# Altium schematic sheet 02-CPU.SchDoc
size A2
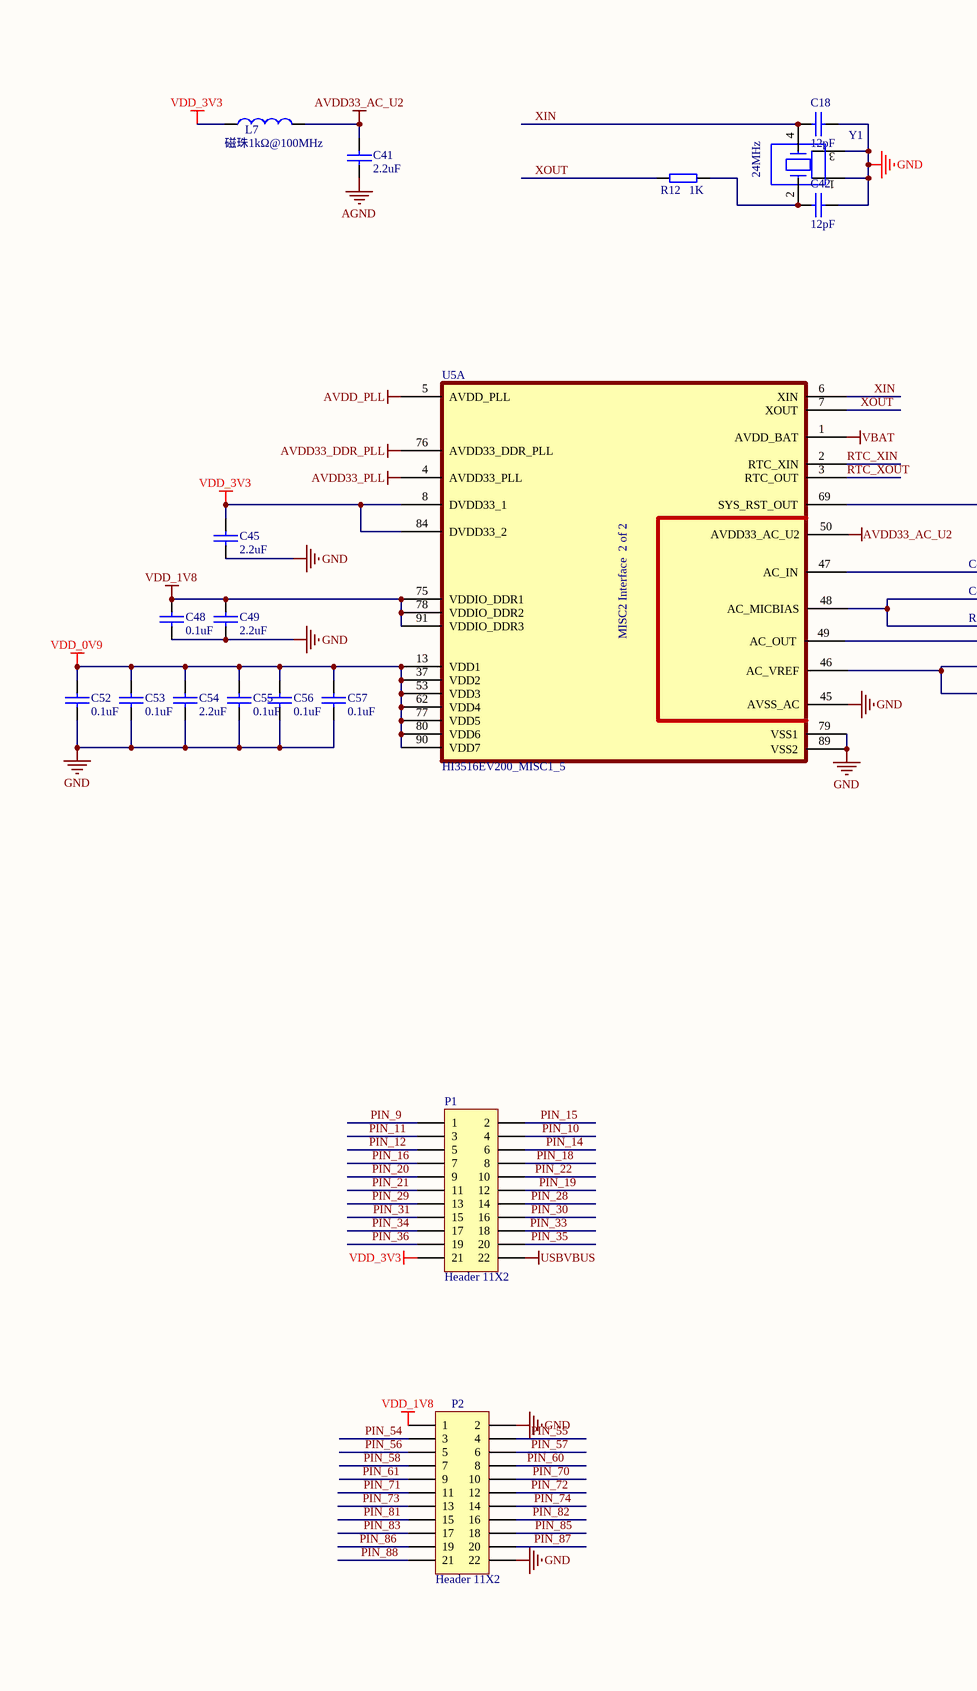
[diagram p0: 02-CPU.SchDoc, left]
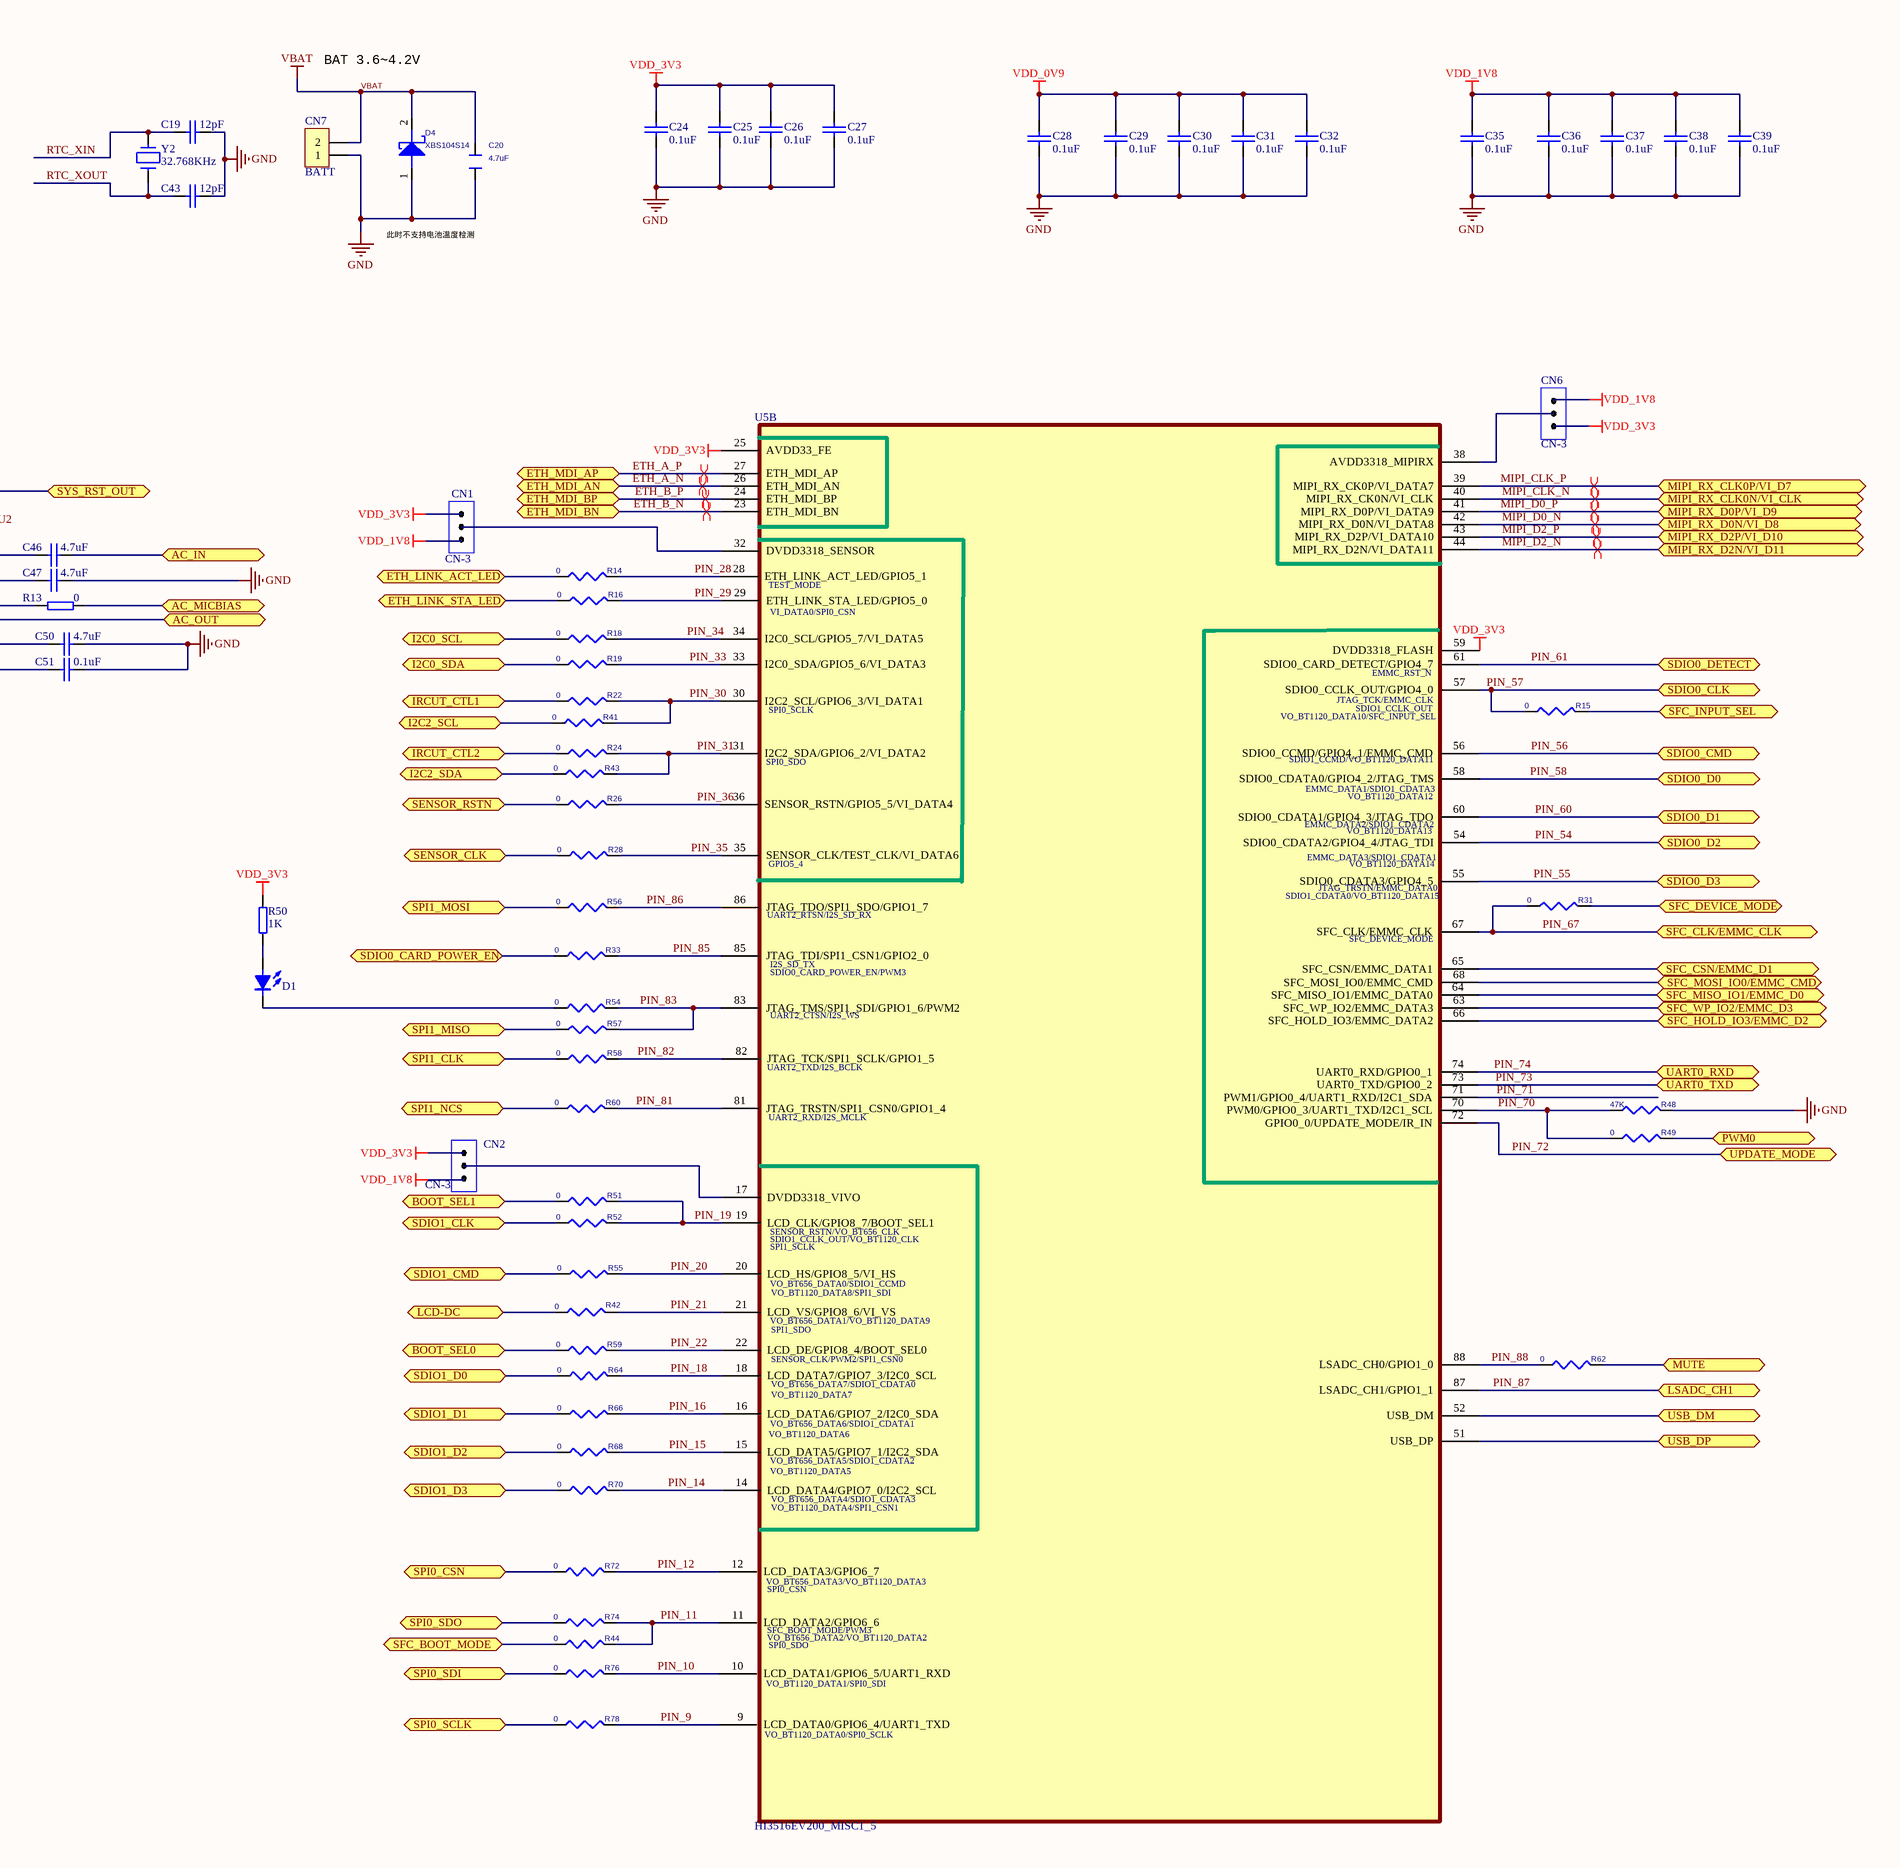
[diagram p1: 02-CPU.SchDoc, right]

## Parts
C18  12pF  [C0402]
C19  12pF  [C0402]
C20  4.7uF  [C0402]
C24  0.1uF  [C0402]
C25  0.1uF  [C0402]
C26  0.1uF  [C0402]
C27  0.1uF  [C0402]
C28  0.1uF  [C0402]
C29  0.1uF  [C0402]
C30  0.1uF  [C0402]
C31  0.1uF  [C0402]
C32  0.1uF  [C0402]
C35  0.1uF  [C0402]
C36  0.1uF  [C0402]
C37  0.1uF  [C0402]
C38  0.1uF  [C0402]
C39  0.1uF  [C0402]
C41  2.2uF  [C0402]
C42  12pF  [C0402]
C43  12pF  [C0402]
C45  2.2uF  [C0402]
C46  4.7uF  [C0402]
C47  4.7uF  [C0402]
C48  0.1uF  [C0402]
C49  2.2uF  [C0402]
C50  4.7uF  [C0402]
C51  0.1uF  [C0402]
C52  0.1uF  [C0402]
C53  0.1uF  [C0402]
C54  2.2uF  [C0402]
C55  0.1uF  [C0402]
C56  0.1uF  [C0402]
C57  0.1uF  [C0402]
CN1  CN-3  [SIP3(1.27_SMD)]
CN2  CN-3  [SIP3(1.27_SMD)]
CN6  CN-3  [SIP3(1.27_SMD)]
CN7  BATT  [PH-2A]
D1  二极管(LED,红色)  [D0603]  (value not drawn)
D4  XBS104S14  [SOD-123]
L7  磁珠1kΩ@100MHz  [L0603]
P1  Header 11X2  [HDR2X11]
P2  Header 11X2  [HDR2X11]
R12  1K  [R0402]
R13  0  [R0402]
R14  0  [R0402]
R15  0  [R0402]
R16  0  [R0402]
R18  0  [R0402]
R19  0  [R0402]
R22  0  [R0402]
R24  0  [R0402]
R26  0  [R0402]
R28  0  [R0402]
R31  0  [R0402]
R33  0  [R0402]
R41  0  [R0402]
R42  0  [R0402]
R43  0  [R0402]
R44  0  [R0402]
R48  47K  [R0402]
R49  0  [R0402]
R50  1K  [R0402]
R51  0  [R0402]
R52  0  [R0402]
R54  0  [R0402]
R55  0  [R0402]
R56  0  [R0402]
R57  0  [R0402]
R58  0  [R0402]
R59  0  [R0402]
R60  0  [R0402]
R62  0  [R0402]
R64  0  [R0402]
R66  0  [R0402]
R68  0  [R0402]
R70  0  [R0402]
R72  0  [R0402]
R74  0  [R0402]
R76  0  [R0402]
R78  0  [R0402]
U5  HI3516EV200_MISC1_5  [V200_MLF88-035-0909L]  (parts A,B of 2)
Y1  24MHz  [XTAL(3*2.5)]
Y2  32.768KHz  [FC-135]

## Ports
AC_IN (bidir), AC_MICBIAS (bidir), AC_OUT (bidir), BOOT_SEL0 (bidir), BOOT_SEL1 (bidir), ETH_LINK_ACT_LED (bidir), ETH_LINK_STA_LED (bidir), ETH_MDI_AN (bidir), ETH_MDI_AP (bidir), ETH_MDI_BN (bidir), ETH_MDI_BP (bidir), I2C0_SCL (bidir), I2C0_SDA (bidir), I2C2_SCL (bidir), I2C2_SDA (bidir), IRCUT_CTL1 (bidir), IRCUT_CTL2 (bidir), LCD-DC (bidir), LSADC_CH1 (bidir), MIPI_RX_CLK0N/VI_CLK (bidir), MIPI_RX_CLK0P/VI_D7 (bidir), MIPI_RX_D0N/VI_D8 (bidir), MIPI_RX_D0P/VI_D9 (bidir), MIPI_RX_D2N/VI_D11 (bidir), MIPI_RX_D2P/VI_D10 (bidir), MUTE (bidir), PWM0 (bidir), SDIO0_CARD_POWER_EN (bidir), SDIO0_CLK (bidir), SDIO0_CMD (bidir), SDIO0_D0 (bidir), SDIO0_D1 (bidir), SDIO0_D2 (bidir), SDIO0_D3 (bidir), SDIO0_DETECT (bidir), SDIO1_CLK (bidir), SDIO1_CMD (bidir), SDIO1_D0 (bidir), SDIO1_D1 (bidir), SDIO1_D2 (bidir), SDIO1_D3 (bidir), SENSOR_CLK (bidir), SENSOR_RSTN (bidir), SFC_BOOT_MODE (bidir), SFC_CLK/EMMC_CLK (bidir), SFC_CSN/EMMC_D1 (bidir), SFC_DEVICE_MODE (bidir), SFC_HOLD_IO3/EMMC_D2 (bidir), SFC_INPUT_SEL (bidir), SFC_MISO_IO1/EMMC_D0 (bidir), SFC_MOSI_IO0/EMMC_CMD (bidir), SFC_WP_IO2/EMMC_D3 (bidir), SPI0_CSN (bidir), SPI0_SCLK (bidir), SPI0_SDI (bidir), SPI0_SDO (bidir), SPI1_CLK (bidir), SPI1_MISO (bidir), SPI1_MOSI (bidir), SPI1_NCS (bidir), SYS_RST_OUT (bidir), UART0_RXD (bidir), UART0_TXD (bidir), UPDATE_MODE (bidir), USB_DM (bidir), USB_DP (bidir)

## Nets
AGND: C41.2
AVDD33_AC_U2: C41.1 L7.2 U5.50(AVDD33_AC_U2)
AVDD33_DDR_PLL: U5.76(AVDD33_DDR_PLL)
AVDD33_PLL: U5.4(AVDD33_PLL)
AVDD_PLL: U5.5(AVDD_PLL)
GND: C18.2 C19.2 C20.1 C24.1 C25.1 C26.1 C27.1 C28.1 C29.1 C30.1 C31.1 C32.1 C35.1 C36.1 C37.1 C38.1 C39.1 C42.2 C43.2 C45.1 C47.2 C48.2 C49.1 C50.2 C51.2 C52.2 C53.2 C54.1 C55.2 C56.2 C57.2 CN7.1 D4.1 P2.2 P2.22 R48.1 U5.45(AVSS_AC) U5.79(VSS1) U5.89(VSS2) Y1.1 Y1.3
USBVBUS: P1.22
VBAT: C20.2 CN7.2 D4.2 U5.1(AVDD_BAT)
VDD_0V9: C28.2 C29.2 C30.2 C31.2 C32.2 C52.1 C53.1 C54.2 C55.1 C56.1 C57.1 U5.13(VDD1) U5.37(VDD2) U5.53(VDD3) U5.62(VDD4) U5.77(VDD5) U5.80(VDD6) U5.90(VDD7)
VDD_1V8: C35.2 C36.2 C37.2 C38.2 C39.2 C48.1 C49.2 CN1.3 CN2.3 CN6.3 P2.1 U5.75(VDDIO_DDR1) U5.78(VDDIO_DDR2) U5.91(VDDIO_DDR3)
VDD_3V3: C24.2 C25.2 C26.2 C27.2 C45.2 CN1.1 CN2.1 CN6.1 L7.1 P1.21 R50.1 U5.8(DVDD33_1) U5.25(AVDD33_FE) U5.59(DVDD3318_FLASH) U5.84(DVDD33_2)
AC_IN: C46.2 ; port AC_IN
AC_MICBIAS: R13.1 ; port AC_MICBIAS
AC_OUT: U5.49(AC_OUT) ; port AC_OUT
BOOT_SEL0: R59.2 ; port BOOT_SEL0
BOOT_SEL1: R51.2 ; port BOOT_SEL1
ETH_A_N: U5.26(ETH_MDI_AN) ; port ETH_MDI_AN
ETH_A_P: U5.27(ETH_MDI_AP) ; port ETH_MDI_AP
ETH_B_N: U5.23(ETH_MDI_BN) ; port ETH_MDI_BN
ETH_B_P: U5.24(ETH_MDI_BP) ; port ETH_MDI_BP
ETH_LINK_ACT_LED: R14.2 ; port ETH_LINK_ACT_LED
ETH_LINK_STA_LED: R16.2 ; port ETH_LINK_STA_LED
I2C0_SCL: R18.2 ; port I2C0_SCL
I2C0_SDA: R19.2 ; port I2C0_SDA
I2C2_SCL: R41.2 ; port I2C2_SCL
I2C2_SDA: R43.2 ; port I2C2_SDA
IRCUT_CTL1: R22.2 ; port IRCUT_CTL1
IRCUT_CTL2: R24.2 ; port IRCUT_CTL2
LCD-DC: R42.2 ; port LCD-DC
MIPI_CLK_N: U5.40(MIPI_RX_CK0N/VI_CLK) ; port MIPI_RX_CLK0N/VI_CLK
MIPI_CLK_P: U5.39(MIPI_RX_CK0P/VI_DATA7) ; port MIPI_RX_CLK0P/VI_D7
MIPI_D0_N: U5.42(MIPI_RX_D0N/VI_DATA8) ; port MIPI_RX_D0N/VI_D8
MIPI_D0_P: U5.41(MIPI_RX_D0P/VI_DATA9) ; port MIPI_RX_D0P/VI_D9
MIPI_D2_N: U5.44(MIPI_RX_D2N/VI_DATA11) ; port MIPI_RX_D2N/VI_D11
MIPI_D2_P: U5.43(MIPI_RX_D2P/VI_DATA10) ; port MIPI_RX_D2P/VI_D10
MUTE: R62.1 ; port MUTE
PIN_9: P1.1 R78.1 U5.9(LCD_DATA0/GPIO6_4/UART1_TXD)
PIN_10: P1.4 R76.1 U5.10(LCD_DATA1/GPIO6_5/UART1_RXD)
PIN_11: P1.3 R44.1 R74.1 U5.11(LCD_DATA2/GPIO6_6)
PIN_12: P1.5 R72.1 U5.12(LCD_DATA3/GPIO6_7)
PIN_14: P1.6 R70.1 U5.14(LCD_DATA4/GPIO7_0/I2C2_SCL)
PIN_15: P1.2 R68.1 U5.15(LCD_DATA5/GPIO7_1/I2C2_SDA)
PIN_16: P1.7 R66.1 U5.16(LCD_DATA6/GPIO7_2/I2C0_SDA)
PIN_18: P1.8 R64.1 U5.18(LCD_DATA7/GPIO7_3/I2C0_SCL)
PIN_19: P1.12 R51.1 R52.1 U5.19(LCD_CLK/GPIO8_7/BOOT_SEL1)
PIN_20: P1.9 R55.1 U5.20(LCD_HS/GPIO8_5/VI_HS)
PIN_21: P1.11 R42.1 U5.21(LCD_VS/GPIO8_6/VI_VS)
PIN_22: P1.10 R59.1 U5.22(LCD_DE/GPIO8_4/BOOT_SEL0)
PIN_28: P1.14 R14.1 U5.28(ETH_LINK_ACT_LED/GPIO5_1)
PIN_29: P1.13 R16.1 U5.29(ETH_LINK_STA_LED/GPIO5_0)
PIN_30: P1.16 R22.1 R41.1 U5.30(I2C2_SCL/GPIO6_3/VI_DATA1)
PIN_31: P1.15 R24.1 R43.1 U5.31(I2C2_SDA/GPIO6_2/VI_DATA2)
PIN_33: P1.18 R19.1 U5.33(I2C0_SDA/GPIO5_6/VI_DATA3)
PIN_34: P1.17 R18.1 U5.34(I2C0_SCL/GPIO5_7/VI_DATA5)
PIN_35: P1.20 R28.1 U5.35(SENSOR_CLK/TEST_CLK/VI_DATA6)
PIN_36: P1.19 R26.1 U5.36(SENSOR_RSTN/GPIO5_5/VI_DATA4)
PIN_54: P2.3 U5.54(SDIO0_CDATA2/GPIO4_4/JTAG_TDI) ; port SDIO0_D2
PIN_55: P2.4 U5.55(SDIO0_CDATA3/GPIO4_5) ; port SDIO0_D3
PIN_56: P2.5 U5.56(SDIO0_CCMD/GPIO4_1/EMMC_CMD) ; port SDIO0_CMD
PIN_57: P2.6 R15.2 U5.57(SDIO0_CCLK_OUT/GPIO4_0) ; port SDIO0_CLK
PIN_58: P2.7 U5.58(SDIO0_CDATA0/GPIO4_2/JTAG_TMS) ; port SDIO0_D0
PIN_60: P2.8 U5.60(SDIO0_CDATA1/GPIO4_3/JTAG_TDO) ; port SDIO0_D1
PIN_61: P2.9 U5.61(SDIO0_CARD_DETECT/GPIO4_7) ; port SDIO0_DETECT
PIN_67: R31.2 U5.67(SFC_CLK/EMMC_CLK) ; port SFC_CLK/EMMC_CLK
PIN_70: P2.10 R48.2 R49.2 U5.70(PWM0/GPIO0_3/UART1_TXD/I2C1_SCL)
PIN_71: P2.11 U5.71(PWM1/GPIO0_4/UART1_RXD/I2C1_SDA)
PIN_72: P2.12 U5.72(GPIO0_0/UPDATE_MODE/IR_IN) ; port UPDATE_MODE
PIN_73: P2.13 U5.73(UART0_TXD/GPIO0_2) ; port UART0_TXD
PIN_74: P2.14 U5.74(UART0_RXD/GPIO0_1) ; port UART0_RXD
PIN_81: P2.15 R60.1 U5.81(JTAG_TRSTN/SPI1_CSN0/GPIO1_4)
PIN_82: P2.16 R58.1 U5.82(JTAG_TCK/SPI1_SCLK/GPIO1_5)
PIN_83: P2.17 R54.1 R57.1 U5.83(JTAG_TMS/SPI1_SDI/GPIO1_6/PWM2)
PIN_85: P2.18 R33.1 U5.85(JTAG_TDI/SPI1_CSN1/GPIO2_0)
PIN_86: P2.19 R56.1 U5.86(JTAG_TDO/SPI1_SDO/GPIO1_7)
PIN_87: P2.20 U5.87(LSADC_CH1/GPIO1_1) ; port LSADC_CH1
PIN_88: P2.21 R62.2 U5.88(LSADC_CH0/GPIO1_0)
PWM0: R49.1 ; port PWM0
RTC_XIN: C19.1 U5.2(RTC_XIN) Y2.2
RTC_XOUT: C43.1 U5.3(RTC_OUT) Y2.1
SDIO0_CARD_POWER_EN: R33.2 ; port SDIO0_CARD_POWER_EN
SDIO1_CLK: R52.2 ; port SDIO1_CLK
SDIO1_CMD: R55.2 ; port SDIO1_CMD
SDIO1_D0: R64.2 ; port SDIO1_D0
SDIO1_D1: R66.2 ; port SDIO1_D1
SDIO1_D2: R68.2 ; port SDIO1_D2
SDIO1_D3: R70.2 ; port SDIO1_D3
SENSOR_CLK: R28.2 ; port SENSOR_CLK
SENSOR_RSTN: R26.2 ; port SENSOR_RSTN
SFC_BOOT_MODE: R44.2 ; port SFC_BOOT_MODE
SFC_CSN/EMMC_D1: U5.65(SFC_CSN/EMMC_DATA1) ; port SFC_CSN/EMMC_D1
SFC_DEVICE_MODE: R31.1 ; port SFC_DEVICE_MODE
SFC_HOLD_IO3/EMMC_D2: U5.66(SFC_HOLD_IO3/EMMC_DATA2) ; port SFC_HOLD_IO3/EMMC_D2
SFC_INPUT_SEL: R15.1 ; port SFC_INPUT_SEL
SFC_MISO_IO1/EMMC_D0: U5.64(SFC_MISO_IO1/EMMC_DATA0) ; port SFC_MISO_IO1/EMMC_D0
SFC_MOSI_IO0/EMMC_CMD: U5.68(SFC_MOSI_IO0/EMMC_CMD) ; port SFC_MOSI_IO0/EMMC_CMD
SFC_WP_IO2/EMMC_D3: U5.63(SFC_WP_IO2/EMMC_DATA3) ; port SFC_WP_IO2/EMMC_D3
SPI0_CSN: R72.2 ; port SPI0_CSN
SPI0_SCLK: R78.2 ; port SPI0_SCLK
SPI0_SDI: R76.2 ; port SPI0_SDI
SPI0_SDO: R74.2 ; port SPI0_SDO
SPI1_CLK: R58.2 ; port SPI1_CLK
SPI1_MISO: R57.2 ; port SPI1_MISO
SPI1_MOSI: R56.2 ; port SPI1_MOSI
SPI1_NCS: R60.2 ; port SPI1_NCS
SYS_RST_OUT: U5.69(SYS_RST_OUT) ; port SYS_RST_OUT
USB_DM: U5.52(USB_DM) ; port USB_DM
USB_DP: U5.51(USB_DP) ; port USB_DP
XIN: C18.1 U5.6(XIN) Y1.4
XOUT: R12.2 U5.7(XOUT)
NetC42_1: C42.1 R12.1 Y1.2
NetC46_1: C46.1 U5.47(AC_IN)
NetC47_1: C47.1 R13.2 U5.48(AC_MICBIAS)
NetC50_1: C50.1 C51.1 U5.46(AC_VREF)
NetCN1_2: CN1.2 U5.32(DVDD3318_SENSOR)
NetCN2_2: CN2.2 U5.17(DVDD3318_VIVO)
NetCN6_2: CN6.2 U5.38(AVDD3318_MIPIRX)
NetD1_1: D1.1(A) R50.2
NetD1_2: D1.2(K) R54.2

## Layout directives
differential pair: ETH_A_N, ETH_A_P, ETH_B_N, ETH_B_P, MIPI_CLK_N, MIPI_CLK_P, MIPI_D0_N, MIPI_D0_P, MIPI_D2_N, MIPI_D2_P

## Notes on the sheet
- BAT 3.6~4.2V
- 此时不支持电池温度检测

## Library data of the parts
C18 C19 C24-C32 C35-C39 C41-C43 C45-C57 = 电容: Capacitor
C20 = CAPACITOR_Dup1: Page: 7
CN7 = CN-2
D1 = 二极管(LED): Light-Emitting Diode
D4 = DIODE_SCHOTTKY: Page: 7
L7 = 电感: Inductor
P1 P2 = Header 11X2: Header, 11-Pin, Dual row
R12 R13 R50 = 电阻Ω: Resistor
R14-R16 R18 R19 R22 R24 R26 R28 R31 R33 R41-R44 R48 R49 R51 R52 R54-R60 R62 R64 R66 R68 R70 R72 R74 R76 R78 = R_Dup4: PAGE: 5; ROOM: DCDC
Y1 = 无源矩形晶振
Y2 = 晶体谐振器: Crystal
